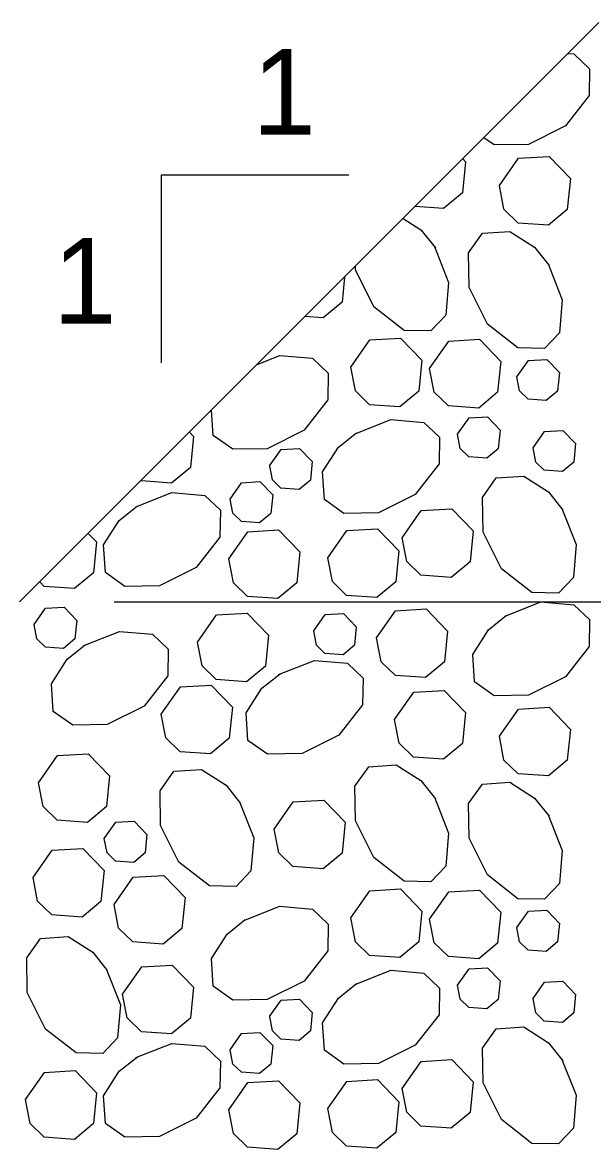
# Model space of a CAD drawing. Extents: x 638079 to 640019, y 297691 to 298879.
# Drawn here: x 639799.91 to 639819.9, y 298741.74 to 298781.25 of the extents above; entities that cross this region are included whole.
import ezdxf

# ---------------------------------------------------------------- set-up
doc = ezdxf.new("R2010")
doc.units = 0
doc.layers.add('1', color=7, linetype='Continuous')

msp = doc.modelspace()

# ---------------------------------------------------------------- linework, layer by layer
at = {"layer": '1'}
for p, q in [((639799.806, 298760.936), (639820.124, 298781.254)), ((639804.763, 298775.907), (639804.763, 298769.322)), ((639811.348, 298775.907), (639804.763, 298775.907)), ((639803.122, 298760.936), (639895.12, 298760.936))]:
    msp.add_line(p, q, dxfattribs=at)
for points in [[(639819.039, 298780.169), (639819.245, 298780.151), (639819.794, 298779.629), (639819.777, 298778.692), (639818.944, 298777.626), (639817.656, 298776.982), (639816.442, 298776.961), (639816.085, 298777.215)], [(639815.344, 298776.474), (639815.445, 298776.369), (639815.337, 298775.285), (639814.674, 298774.733), (639813.675, 298774.805)], [(639816.629, 298775.539), (639817.301, 298776.495), (639818.375, 298776.557), (639819.121, 298775.783), (639819.013, 298774.699), (639818.35, 298774.147), (639817.29, 298774.224), (639816.792, 298774.708), (639816.63, 298775.539)], [(639813.254, 298774.384), (639813.878, 298773.985), (639814.385, 298773.35)], [(639818.338, 298772.79), (639818.837, 298771.533), (639818.737, 298770.377), (639818.215, 298769.828), (639817.278, 298769.846), (639816.212, 298770.679), (639815.569, 298771.967), (639815.547, 298773.181), (639816.033, 298773.864), (639816.999, 298773.929), (639817.864, 298773.375), (639818.371, 298772.74)], [(639814.353, 298773.4), (639814.851, 298772.143), (639814.751, 298770.987), (639814.229, 298770.438), (639813.292, 298770.456), (639812.227, 298771.289), (639811.583, 298772.577), (639811.58, 298772.711)], [(639811.2, 298772.33), (639811.112, 298771.446), (639810.449, 298770.895), (639809.81, 298770.941)], [(639811.418, 298769.169), (639812.09, 298770.125), (639813.164, 298770.186), (639813.91, 298769.413), (639813.802, 298768.329), (639813.139, 298767.777), (639812.079, 298767.854), (639811.581, 298768.337), (639811.419, 298769.168)], [(639814.184, 298769.128), (639814.856, 298770.084), (639815.929, 298770.146), (639816.676, 298769.372), (639816.568, 298768.288), (639815.904, 298767.736), (639814.845, 298767.813), (639814.346, 298768.297), (639814.184, 298769.128)], [(639808.136, 298769.267), (639808.926, 298769.58), (639810.081, 298769.48), (639810.63, 298768.958), (639810.613, 298768.02), (639809.779, 298766.955), (639808.491, 298766.311), (639807.278, 298766.29), (639806.594, 298766.775), (639806.535, 298767.665)], [(639817.243, 298768.833), (639817.646, 298769.406), (639818.29, 298769.443), (639818.738, 298768.979), (639818.673, 298768.329), (639818.275, 298767.998), (639817.639, 298768.044), (639817.34, 298768.334), (639817.243, 298768.832)], [(639811.57, 298766.835), (639812.828, 298767.333), (639813.983, 298767.233), (639814.532, 298766.711), (639814.515, 298765.774), (639813.681, 298764.708), (639812.393, 298764.065), (639811.18, 298764.043), (639810.496, 298764.529), (639810.432, 298765.496), (639810.986, 298766.36), (639811.621, 298766.867)], [(639815.162, 298766.815), (639815.565, 298767.389), (639816.209, 298767.426), (639816.657, 298766.961), (639816.592, 298766.311), (639816.194, 298765.98), (639815.558, 298766.026), (639815.259, 298766.316), (639815.162, 298766.815)], [(639805.761, 298766.891), (639805.906, 298766.74), (639805.798, 298765.656), (639805.135, 298765.105), (639804.075, 298765.181), (639804.063, 298765.193)], [(639817.81, 298766.342), (639818.213, 298766.916), (639818.857, 298766.953), (639819.305, 298766.488), (639819.24, 298765.838), (639818.843, 298765.507), (639818.207, 298765.553), (639817.907, 298765.843), (639817.81, 298766.342)], [(639808.573, 298765.712), (639808.977, 298766.286), (639809.621, 298766.322), (639810.068, 298765.858), (639810.004, 298765.208), (639809.606, 298764.877), (639808.97, 298764.923), (639808.671, 298765.213), (639808.574, 298765.712)], [(639818.826, 298764.209), (639819.325, 298762.951), (639819.225, 298761.796), (639818.703, 298761.247), (639817.765, 298761.264), (639816.7, 298762.098), (639816.056, 298763.386), (639816.035, 298764.599), (639816.52, 298765.283), (639817.487, 298765.347), (639818.352, 298764.793), (639818.858, 298764.158)], [(639807.186, 298764.545), (639807.59, 298765.119), (639808.234, 298765.156), (639808.681, 298764.692), (639808.617, 298764.041), (639808.219, 298763.71), (639807.583, 298763.756), (639807.284, 298764.046), (639807.187, 298764.545)], [(639803.884, 298764.273), (639805.142, 298764.771), (639806.297, 298764.671), (639806.846, 298764.149), (639806.829, 298763.212), (639805.995, 298762.147), (639804.708, 298761.503), (639803.494, 298761.481), (639802.811, 298761.967), (639802.746, 298762.934), (639803.3, 298763.798), (639803.935, 298764.305)], [(639813.217, 298763.184), (639813.889, 298764.141), (639814.963, 298764.202), (639815.709, 298763.428), (639815.601, 298762.344), (639814.938, 298761.793), (639813.878, 298761.87), (639813.38, 298762.353), (639813.218, 298763.184)], [(639802.211, 298763.341), (639802.499, 298763.042), (639802.391, 298761.958), (639801.728, 298761.407), (639800.668, 298761.483), (639800.508, 298761.638)], [(639807.141, 298762.444), (639807.814, 298763.4), (639808.887, 298763.461), (639809.633, 298762.688), (639809.525, 298761.603), (639808.862, 298761.052), (639807.802, 298761.129), (639807.304, 298761.612), (639807.142, 298762.443)], [(639810.61, 298762.483), (639811.282, 298763.439), (639812.356, 298763.501), (639813.102, 298762.727), (639812.994, 298761.643), (639812.331, 298761.091), (639811.271, 298761.168), (639810.772, 298761.652), (639810.611, 298762.483)], [(639816.832, 298760.438), (639818.09, 298760.936), (639819.245, 298760.837), (639819.794, 298760.315), (639819.777, 298759.377), (639818.944, 298758.312), (639817.656, 298757.668), (639816.442, 298757.647), (639815.759, 298758.132), (639815.694, 298759.099), (639816.248, 298759.964), (639816.883, 298760.47)], [(639800.314, 298760.142), (639800.717, 298760.716), (639801.361, 298760.752), (639801.809, 298760.288), (639801.744, 298759.638), (639801.346, 298759.307), (639800.71, 298759.353), (639800.411, 298759.643), (639800.314, 298760.142)], [(639806.039, 298759.528), (639806.711, 298760.484), (639807.784, 298760.546), (639808.531, 298759.772), (639808.423, 298758.688), (639807.76, 298758.136), (639806.7, 298758.213), (639806.201, 298758.697), (639806.039, 298759.528)], [(639810.118, 298759.921), (639810.521, 298760.495), (639811.165, 298760.532), (639811.613, 298760.067), (639811.548, 298759.417), (639811.151, 298759.086), (639810.514, 298759.132), (639810.215, 298759.422), (639810.118, 298759.921)], [(639812.321, 298759.673), (639812.993, 298760.63), (639814.067, 298760.691), (639814.813, 298759.917), (639814.705, 298758.833), (639814.042, 298758.282), (639812.982, 298758.358), (639812.483, 298758.842), (639812.322, 298759.673)], [(639802.056, 298759.405), (639803.313, 298759.904), (639804.469, 298759.804), (639805.018, 298759.282), (639805, 298758.345), (639804.167, 298757.279), (639802.879, 298756.635), (639801.665, 298756.614), (639800.982, 298757.1), (639800.917, 298758.066), (639801.472, 298758.931), (639802.107, 298759.438)], [(639808.888, 298758.389), (639810.146, 298758.887), (639811.301, 298758.787), (639811.85, 298758.265), (639811.833, 298757.328), (639810.999, 298756.263), (639809.711, 298755.619), (639808.498, 298755.597), (639807.814, 298756.083), (639807.75, 298757.05), (639808.304, 298757.914), (639808.939, 298758.421)], [(639804.774, 298756.998), (639805.446, 298757.954), (639806.519, 298758.016), (639807.266, 298757.242), (639807.158, 298756.158), (639806.495, 298755.606), (639805.435, 298755.683), (639804.936, 298756.167), (639804.774, 298756.998)], [(639812.954, 298756.81), (639813.626, 298757.767), (639814.699, 298757.828), (639815.445, 298757.054), (639815.337, 298755.97), (639814.674, 298755.419), (639813.615, 298755.495), (639813.116, 298755.979), (639812.954, 298756.81)], [(639816.629, 298756.225), (639817.301, 298757.181), (639818.375, 298757.242), (639819.121, 298756.469), (639819.013, 298755.385), (639818.35, 298754.833), (639817.29, 298754.91), (639816.792, 298755.393), (639816.63, 298756.224)], [(639800.463, 298754.598), (639801.135, 298755.555), (639802.208, 298755.616), (639802.955, 298754.842), (639802.847, 298753.758), (639802.184, 298753.207), (639801.124, 298753.283), (639800.625, 298753.767), (639800.463, 298754.598)], [(639807.52, 298753.923), (639808.019, 298752.666), (639807.919, 298751.51), (639807.397, 298750.961), (639806.459, 298750.979), (639805.394, 298751.812), (639804.75, 298753.1), (639804.729, 298754.314), (639805.214, 298754.997), (639806.181, 298755.061), (639807.046, 298754.507), (639807.552, 298753.872)], [(639814.353, 298754.086), (639814.851, 298752.828), (639814.751, 298751.673), (639814.229, 298751.124), (639813.292, 298751.141), (639812.227, 298751.975), (639811.583, 298753.263), (639811.561, 298754.476), (639812.047, 298755.16), (639813.014, 298755.224), (639813.878, 298754.67), (639814.385, 298754.035)], [(639818.338, 298753.476), (639818.837, 298752.218), (639818.737, 298751.063), (639818.215, 298750.514), (639817.278, 298750.531), (639816.212, 298751.365), (639815.569, 298752.653), (639815.547, 298753.866), (639816.033, 298754.55), (639816.999, 298754.614), (639817.864, 298754.06), (639818.371, 298753.425)], [(639808.728, 298752.972), (639809.4, 298753.928), (639810.473, 298753.989), (639811.22, 298753.216), (639811.112, 298752.132), (639810.449, 298751.58), (639809.389, 298751.657), (639808.89, 298752.14), (639808.728, 298752.972)], [(639802.773, 298752.639), (639803.176, 298753.213), (639803.82, 298753.25), (639804.268, 298752.785), (639804.203, 298752.135), (639803.805, 298751.804), (639803.169, 298751.85), (639802.87, 298752.14), (639802.773, 298752.639)], [(639800.275, 298751.278), (639800.947, 298752.234), (639802.02, 298752.295), (639802.766, 298751.522), (639802.658, 298750.437), (639801.995, 298749.886), (639800.935, 298749.963), (639800.437, 298750.446), (639800.275, 298751.277)], [(639803.115, 298750.328), (639803.788, 298751.284), (639804.861, 298751.346), (639805.607, 298750.572), (639805.499, 298749.488), (639804.836, 298748.936), (639803.776, 298749.013), (639803.278, 298749.497), (639803.116, 298750.328)], [(639811.418, 298749.854), (639812.09, 298750.811), (639813.164, 298750.872), (639813.91, 298750.098), (639813.802, 298749.014), (639813.139, 298748.463), (639812.079, 298748.539), (639811.581, 298749.023), (639811.419, 298749.854)], [(639814.184, 298749.813), (639814.856, 298750.77), (639815.929, 298750.831), (639816.676, 298750.057), (639816.568, 298748.973), (639815.904, 298748.422), (639814.845, 298748.499), (639814.346, 298748.982), (639814.184, 298749.813)], [(639807.668, 298749.767), (639808.926, 298750.265), (639810.081, 298750.165), (639810.63, 298749.643), (639810.613, 298748.706), (639809.779, 298747.641), (639808.491, 298746.997), (639807.278, 298746.975), (639806.594, 298747.461), (639806.53, 298748.428), (639807.084, 298749.292), (639807.719, 298749.799)], [(639817.243, 298749.518), (639817.646, 298750.092), (639818.29, 298750.129), (639818.738, 298749.664), (639818.673, 298749.014), (639818.275, 298748.683), (639817.639, 298748.729), (639817.34, 298749.019), (639817.243, 298749.518)], [(639802.843, 298748.067), (639803.342, 298746.809), (639803.242, 298745.654), (639802.72, 298745.105), (639801.782, 298745.122), (639800.717, 298745.956), (639800.073, 298747.243), (639800.052, 298748.457), (639800.537, 298749.14), (639801.504, 298749.205), (639802.369, 298748.651), (639802.875, 298748.016)], [(639803.414, 298747.182), (639804.087, 298748.138), (639805.16, 298748.199), (639805.906, 298747.426), (639805.798, 298746.342), (639805.135, 298745.79), (639804.075, 298745.867), (639803.577, 298746.35), (639803.415, 298747.182)], [(639811.57, 298747.52), (639812.828, 298748.019), (639813.983, 298747.919), (639814.532, 298747.397), (639814.515, 298746.459), (639813.681, 298745.394), (639812.393, 298744.75), (639811.18, 298744.729), (639810.496, 298745.214), (639810.432, 298746.181), (639810.986, 298747.046), (639811.621, 298747.552)], [(639815.162, 298747.5), (639815.565, 298748.074), (639816.209, 298748.111), (639816.657, 298747.647), (639816.592, 298746.996), (639816.194, 298746.665), (639815.558, 298746.712), (639815.259, 298747.002), (639815.162, 298747.5)], [(639817.81, 298747.028), (639818.213, 298747.601), (639818.857, 298747.638), (639819.305, 298747.174), (639819.24, 298746.524), (639818.843, 298746.193), (639818.207, 298746.239), (639817.907, 298746.529), (639817.81, 298747.027)], [(639808.573, 298746.397), (639808.977, 298746.971), (639809.621, 298747.008), (639810.068, 298746.544), (639810.004, 298745.893), (639809.606, 298745.562), (639808.97, 298745.608), (639808.671, 298745.898), (639808.574, 298746.397)], [(639818.826, 298744.894), (639819.325, 298743.637), (639819.225, 298742.481), (639818.703, 298741.932), (639817.765, 298741.95), (639816.7, 298742.783), (639816.056, 298744.071), (639816.035, 298745.285), (639816.52, 298745.968), (639817.487, 298746.033), (639818.352, 298745.479), (639818.858, 298744.844)], [(639807.186, 298745.231), (639807.59, 298745.805), (639808.234, 298745.841), (639808.681, 298745.377), (639808.617, 298744.727), (639808.219, 298744.396), (639807.583, 298744.442), (639807.284, 298744.732), (639807.187, 298745.231)], [(639803.884, 298744.958), (639805.142, 298745.457), (639806.297, 298745.357), (639806.846, 298744.835), (639806.829, 298743.897), (639805.995, 298742.832), (639804.708, 298742.188), (639803.494, 298742.167), (639802.811, 298742.652), (639802.746, 298743.619), (639803.3, 298744.484), (639803.935, 298744.99)], [(639813.217, 298743.87), (639813.889, 298744.826), (639814.963, 298744.888), (639815.709, 298744.114), (639815.601, 298743.03), (639814.938, 298742.478), (639813.878, 298742.555), (639813.38, 298743.039), (639813.218, 298743.87)], [(639800.007, 298743.484), (639800.68, 298744.44), (639801.753, 298744.501), (639802.499, 298743.728), (639802.391, 298742.644), (639801.728, 298742.092), (639800.668, 298742.169), (639800.17, 298742.652), (639800.008, 298743.484)], [(639807.141, 298743.129), (639807.814, 298744.085), (639808.887, 298744.147), (639809.633, 298743.373), (639809.525, 298742.289), (639808.862, 298741.737), (639807.802, 298741.814), (639807.304, 298742.298), (639807.142, 298743.129)], [(639810.61, 298743.169), (639811.282, 298744.125), (639812.356, 298744.186), (639813.102, 298743.413), (639812.994, 298742.328), (639812.331, 298741.777), (639811.271, 298741.854), (639810.772, 298742.337), (639810.611, 298743.168)]]:
    msp.add_lwpolyline(points, dxfattribs=at)

# ---------------------------------------------------------------- texts
for p in [(639807.969, 298777.322), (639800.979, 298770.693)]:
    msp.add_text('1', height=3, dxfattribs=at).set_placement(p)

doc.saveas('drawing.dxf')
